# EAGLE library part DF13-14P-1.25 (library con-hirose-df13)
DF13-14P 1.25mm Pitch Miniature Crimping Connector.
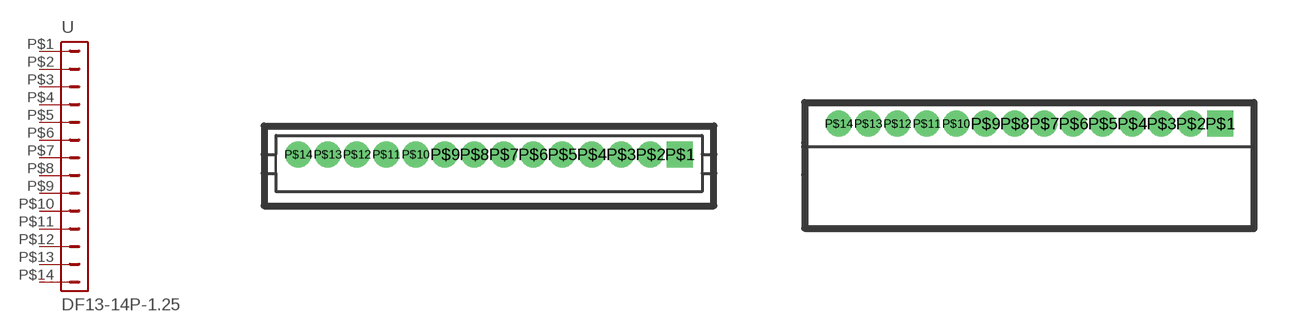
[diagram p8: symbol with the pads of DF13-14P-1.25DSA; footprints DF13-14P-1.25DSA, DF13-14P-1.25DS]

Designator prefix -

## DF13-14P-1.25DSA  [DF13-14P-1.25DSA]
P$1  1  pas
P$2  2  pas
P$3  3  pas
P$4  4  pas
P$5  5  pas
P$6  6  pas
P$7  7  pas
P$8  8  pas
P$9  9  pas
P$10  10  pas
P$11  11  pas
P$12  12  pas
P$13  13  pas
P$14  14  pas

## DF13-14P-1.25DS  [DF13-14P-1.25DS]
Pads as for DF13-14P-1.25DSA

## DF13-14P-1.25V  [DF13C-14P-1.25V]
Pads as for DF13-14P-1.25DSA

## DF13-14P-1.25H  [DF13A-14P-1.25H]
Pads as for DF13-14P-1.25DSA

## Footprint DF13-14P-1.25DSA (pad centres in mm)
Single Row Straight Pin Header (Through hole)
drill 0.6 pad 1.016 square: P$1 8.125,0
drill 0.6 pad 1.016 round: P$2 6.875,0; P$3 5.625,0; P$4 4.375,0; P$5 3.125,0; P$6 1.875,0; P$7 0.625,0; P$8 -0.625,0; P$9 -1.875,0; P$10 -3.125,0; P$11 -4.375,0; P$12 -5.625,0; P$13 -6.875,0; P$14 -8.125,0

## Footprint DF13-14P-1.25DS (pad centres in mm)
Single Row Right Angle Pin Header (Through hole)
drill 0.6 pad 1.016 square: P$1 8.125,0
drill 0.6 pad 1.016 round: P$2 6.875,0; P$3 5.625,0; P$4 4.375,0; P$5 3.125,0; P$6 1.875,0; P$7 0.625,0; P$8 -0.625,0; P$9 -1.875,0; P$10 -3.125,0; P$11 -4.375,0; P$12 -5.625,0; P$13 -6.875,0; P$14 -8.125,0

## Footprint DF13C-14P-1.25V (pad centres in mm)
Single Row Straight Pin Header (SMT)
smd 1.6 x 2.2: M$0 10.575,-1.8; M$1 -10.575,-1.8
smd 0.7 x 1.8: P$1 -8.125,0.9; P$2 -6.875,0.9; P$3 -5.625,0.9; P$4 -4.375,0.9; P$5 -3.125,0.9; P$6 -1.875,0.9; P$7 -0.625,0.9; P$8 0.625,0.9; P$9 1.875,0.9; P$10 3.125,0.9; P$11 4.375,0.9; P$12 5.625,0.9; P$13 6.875,0.9; P$14 8.125,0.9

## Footprint DF13A-14P-1.25H (pad centres in mm)
Single Row Straight Pin Header (SMT)
smd 1.6 x 2.2: M$0 -10.475,2.4; M$1 10.475,2.4
smd 0.7 x 1.8: P$1 -8.125,-0.9; P$2 -6.875,-0.9; P$3 -5.625,-0.9; P$4 -4.375,-0.9; P$5 -3.15,-0.9; P$6 -1.875,-0.9; P$7 -0.625,-0.9; P$8 0.625,-0.9; P$9 1.85,-0.9; P$10 3.125,-0.9; P$11 4.375,-0.9; P$12 5.625,-0.9; P$13 6.875,-0.9; P$14 8.125,-0.9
